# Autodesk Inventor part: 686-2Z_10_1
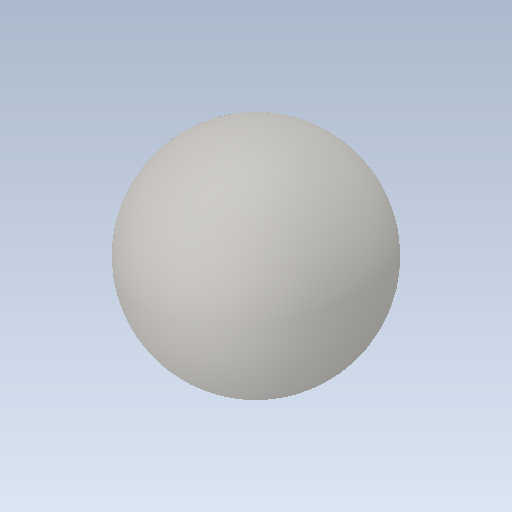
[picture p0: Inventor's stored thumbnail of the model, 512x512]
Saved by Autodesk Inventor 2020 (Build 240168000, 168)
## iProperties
Created: 2017-11
Part Number: 686-2Z_10_1
Material: Ogólny
Document SubType Name: Modeling
Designer: Tomasz
Density: 1 g/cm^3
Appearance: Domyślna
Sending System: SolidWorks 2017
Last Author: Tomasz
Last Saved: 2017-11-19
Source: 686-2Z_10_1
Author: Tomasz
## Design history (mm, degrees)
feature "Imported1"
node "Bryła1"
